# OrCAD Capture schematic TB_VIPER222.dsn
size D
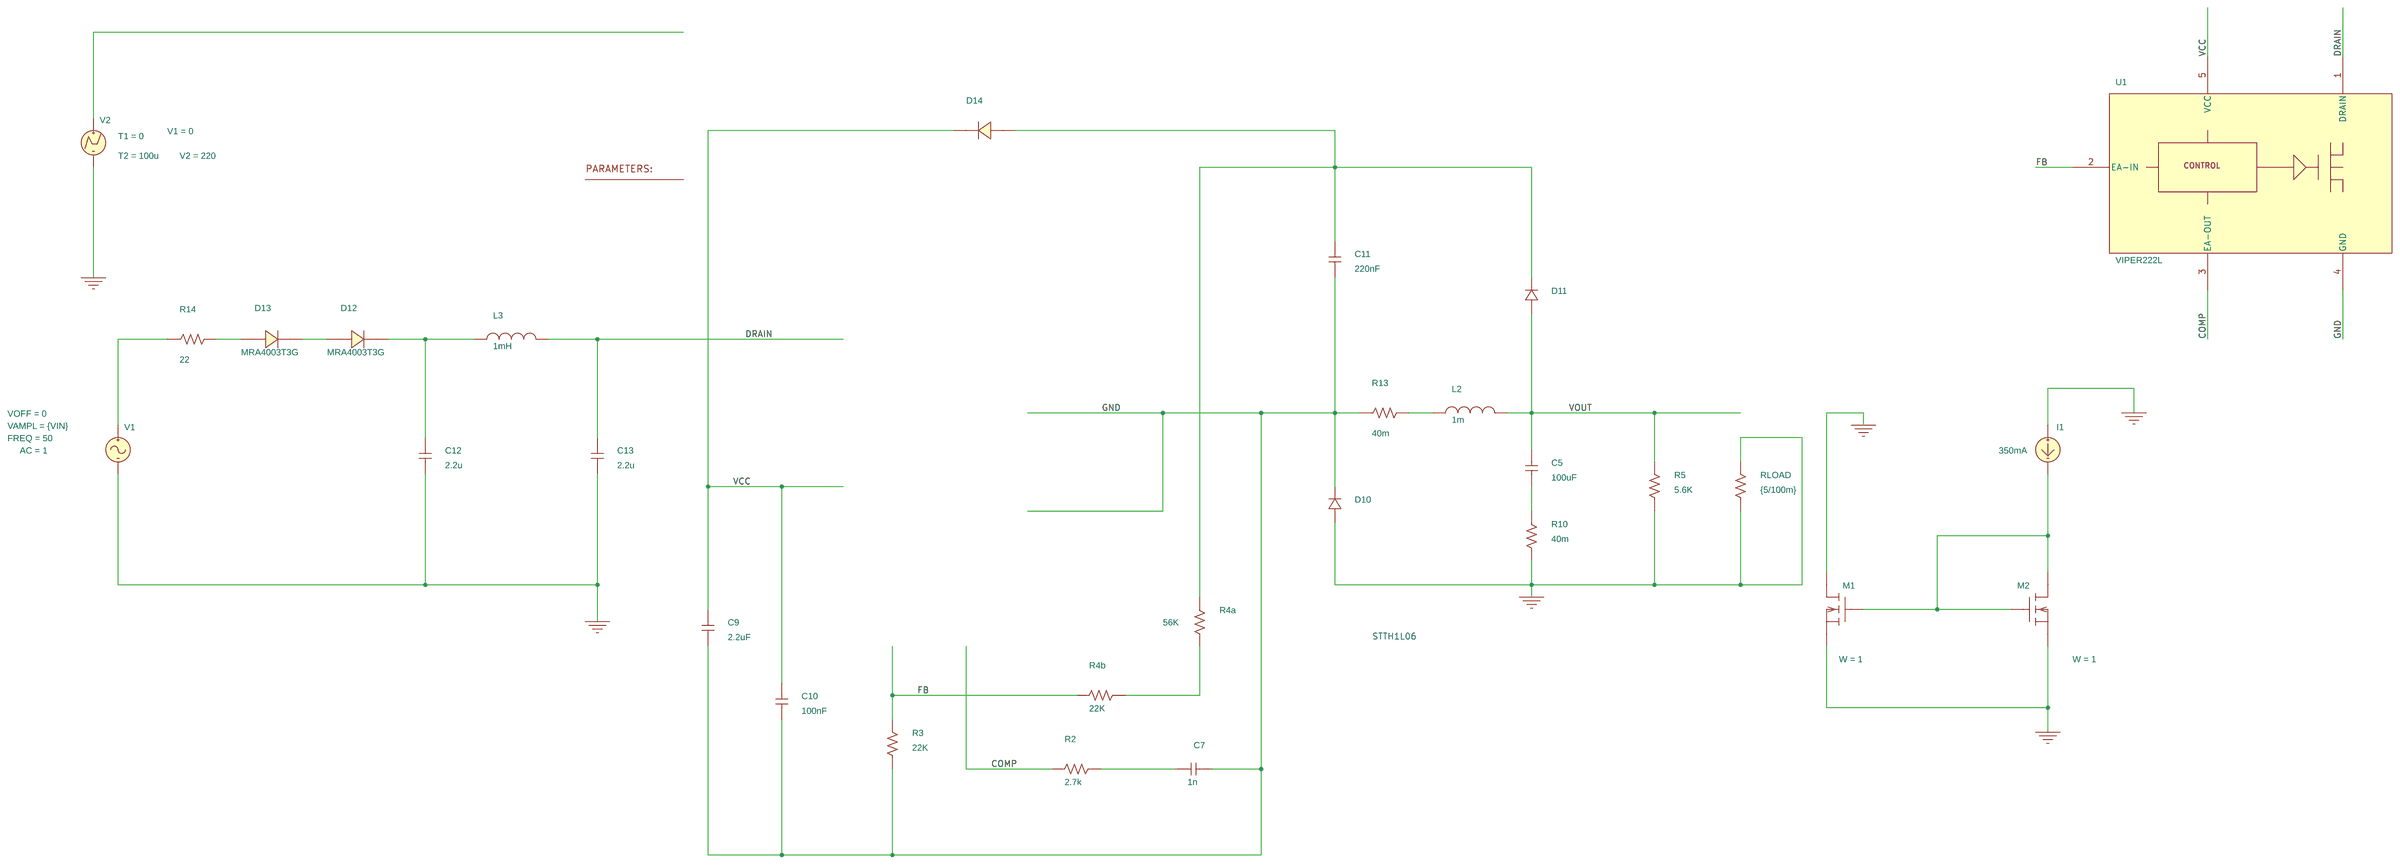
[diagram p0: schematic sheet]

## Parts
2  PARAM
C5  100uF  [CK05]
C7  1n  [CK05]
C9  2.2uF  [CK05]
C10  100nF  [CK05]
C11  220nF  [RAD/CK05]
C12  2.2u  [RAD/CK05]
C13  2.2u  [RAD/CK05]
D10  Dbreak
D11  Dbreak
D12  MRA4003T3G  [SMA403D]
D13  MRA4003T3G  [SMA403D]
D14  MRA4003T3G  [SMA403D]
I1  IDC
L2  1m  [L2012C]
L3  1mH  [L2012C]
M1  MbreakN3
M2  MbreakN3
R2  2.7k  [RC05]
R3  22K  [RC05]
R4a  56K  [RC05]
R4b  22K  [RC05]
R5  5.6K  [RC05]
R10  40m  [RC05]
R13  40m  [RC05]
R14  22  [RC05]
RLOAD  {5/100m}  [RC05]
U1  VIPER222L
V1  VSIN
V2  VPWL

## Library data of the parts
2 = PARAM: VIN: 220
C5 C7 C9-C13 = C
D10 D11 = Dbreak
D12-D14 = MRA4003T3G
I1 = IDC: DC: 350mA
L2 L3 = L
M1 M2 = MbreakN3: W: 1
R2 R3 R4a R4b R5 R10 R13 R14 RLOAD = R
U1 = VIPER222L
V1 = VSIN: AC: 1; FREQ: 50; VAMPL: {VIN}; VOFF: 0
V2 = VPWL: T1: 0; T2: 100u; V1: 0; V2: 220

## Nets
GND: C7.2 C9.1 C10.1 C11.1 D10.1(2) R3.1 R13.1 U1.4(GND)
VCC: C9.2 C10.2 D14.1(C) U1.5(VCC)
0: C12.1 C13.1 D10.0(1) I1.1(+) M1.0(s) M1.2(d) M2.0(s) R5.1 R10.2 RLOAD.1 RLOAD.2 V1.2(-) V2.2(-)
COMP: R2.2 U1.3(EA-OUT)
DRAIN: C13.2 L3.2 U1.1(DRAIN)
FB: R3.2 R4b.2 U1.2(EA-IN)
VOUT: C5.2 D11.0(1) L2.2 R5.2
N4050928: C11.2 D11.1(2) D14.2(A) R4a.1
N4051142: R14.1 V1.1(+)
N4051152: D13.2(A) R14.2
N4051158: D12.2(A) D13.1(C)
N4051164: C12.2 D12.1(C) L3.1
N4051294: L2.1 R13.2
N4051524: I1.2(-) M1.1(g) M2.1(g) M2.2(d)
N4051550: C5.1 R10.1
N4051804: R4a.2 R4b.1
N4051966: C7.1 R2.1

Not connected (* = marked no-connect by the designer): V2 1(+)

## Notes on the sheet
- STTH1L06
